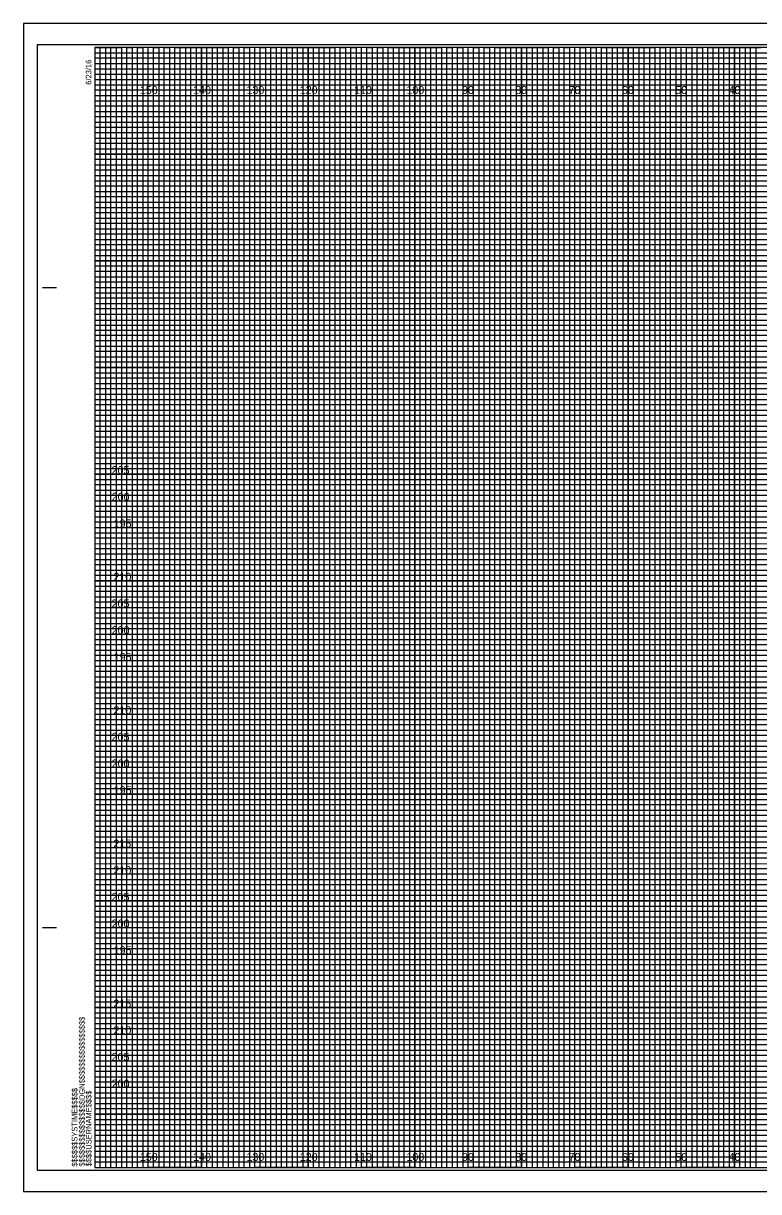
# Model space of a CAD drawing. Extents: x -13 to 323, y -5 to 434.
# Drawn here: x -13.4 to 124.5, y 215.5 to 434.5 of the extents above; entities that cross this region are included whole.
import ezdxf

# ---------------------------------------------------------------- set-up
doc = ezdxf.new("R2010")
doc.units = 0
for name, color, linetype in [('Prop XS Elevation Labels', 7, 'Continuous'), ('Prop XS Offset Labels', 7, 'Continuous'), ('Sheet Cross Section CELL', 7, 'Continuous'), ('Sheet Cross Section Grid Major CELL', 7, 'Continuous'), ('Sheet Cross Section Grid Middle CELL', 7, 'Continuous'), ('Sheet Cross Section Grid Minor 1 CELL', 7, 'Continuous'), ('Sheet Cross Section Grid Minor 2 CELL', 7, 'Continuous'), ('Sheet Cutting Line CELL', 7, 'Continuous'), ('Sheet DOT Grid CELL', 7, 'Continuous'), ('Sheet Plot Border Inside CELL', 7, 'Continuous'), ('Sheet Plot Border Outside CELL', 7, 'Continuous')]:
    doc.layers.add(name, color=color, linetype=linetype)

msp = doc.modelspace()

# ---------------------------------------------------------------- linework, layer by layer
at = {"layer": 'Sheet Cross Section CELL'}
for p, q in [((-9.8, 385), (-7.3, 385)), ((-9.7, 385), (-7.2, 385)), ((-9.8, 265), (-7.3, 265)), ((-9.7, 265), (-7.2, 265)), ((0, 220), (0, 220)), ((0, 220), (0, 220)), ((0, 220), (0, 220)), ((0, 220), (0, 220)), ((0, 220), (0, 220)), ((0, 220), (0, 220)), ((0, 220), (0, 220))]:
    msp.add_line(p, q, dxfattribs=at)
msp.add_lwpolyline([(320, 430), (0, 430), (0, 220), (320, 220)], close=True, dxfattribs=at)
at = {"layer": 'Sheet Cross Section Grid Major CELL'}
for p, q in [((10, 430), (0, 430)), ((10, 220), (10, 430)), ((30, 430), (20, 430)), ((20, 430), (20, 220)), ((30, 220), (30, 430)), ((50, 430), (40, 430)), ((40, 430), (40, 220)), ((50, 220), (50, 430)), ((70, 430), (60, 430)), ((60, 430), (60, 220)), ((70, 220), (70, 430)), ((90, 430), (80, 430)), ((80, 430), (80, 220)), ((90, 220), (90, 430)), ((110, 430), (100, 430)), ((100, 430), (100, 220)), ((110, 220), (110, 430)), ((130, 430), (120, 430)), ((120, 430), (120, 220)), ((20, 220), (10, 220)), ((40, 220), (30, 220)), ((60, 220), (50, 220)), ((80, 220), (70, 220)), ((100, 220), (90, 220)), ((120, 220), (110, 220))]:
    msp.add_line(p, q, dxfattribs=at)
for points in [[(0, 420), (320, 420), (320, 410), (0, 410)], [(0, 400), (320, 400), (320, 390), (0, 390)], [(0, 380), (320, 380), (320, 370), (0, 370)], [(0, 360), (320, 360), (320, 350), (0, 350)], [(0, 340), (320, 340), (320, 330), (0, 330)], [(0, 320), (320, 320), (320, 310), (0, 310)], [(0, 300), (320, 300), (320, 290), (0, 290)], [(0, 280), (320, 280), (320, 270), (0, 270)], [(0, 260), (320, 260), (320, 250), (0, 250)], [(0, 240), (320, 240), (320, 230), (0, 230)]]:
    msp.add_lwpolyline(points, dxfattribs=at)
at = {"layer": 'Sheet Cross Section Grid Middle CELL'}
for points in [[(0, 430), (5, 430), (5, 220), (15, 220), (15, 430), (25, 430), (25, 220), (35, 220), (35, 430), (45, 430), (45, 220), (55, 220), (55, 430), (65, 430), (65, 220), (75, 220), (75, 430), (85, 430), (85, 220), (95, 220), (95, 430), (105, 430), (105, 220), (115, 220), (115, 430), (125, 430)], [(0, 425), (275, 425)], [(0, 405), (320, 405), (320, 415), (0, 415)], [(0, 385), (320, 385), (320, 395), (0, 395)], [(0, 365), (320, 365), (320, 375), (0, 375)], [(0, 345), (320, 345), (320, 355), (0, 355)], [(0, 325), (320, 325), (320, 335), (0, 335)], [(0, 305), (320, 305), (320, 315), (0, 315)], [(0, 285), (320, 285), (320, 295), (0, 295)], [(0, 265), (320, 265), (320, 275), (0, 275)], [(0, 245), (320, 245), (320, 255), (0, 255)], [(0, 225), (320, 225), (320, 235), (0, 235)]]:
    msp.add_lwpolyline(points, dxfattribs=at)
at = {"layer": 'Sheet Cross Section Grid Minor 1 CELL'}
for p, q in [((0, 429), (260, 429)), ((260, 427.98), (0, 427.98)), ((0, 427.98), (0, 427)), ((0, 427), (260, 427)), ((260, 425.89), (0, 425.89)), ((0, 425.89), (0, 424)), ((0, 424), (320, 424))]:
    msp.add_line(p, q, dxfattribs=at)
for points in [[(0, 423), (270, 423), (320, 423), (320, 422), (0, 422)], [(0, 421), (320, 421), (320, 419), (0, 419)], [(0, 418), (320, 418), (320, 417), (0, 416.98)], [(0, 416), (320, 416), (320, 414), (0, 414)], [(0, 413), (320, 413), (320, 412), (0, 412)], [(0, 411), (320, 411), (320, 409), (0, 409)], [(0, 408), (320, 408), (320, 407), (0, 407)], [(0, 406), (320, 406), (320, 404), (0, 404)], [(0, 403), (320, 403), (320, 402), (0, 402)], [(0, 401), (320, 401), (320, 399), (0, 399)], [(0, 398), (320, 398), (320, 397), (0, 397)], [(0, 396), (320, 396), (320, 393.95), (320, 393), (320, 392), (0, 392)], [(0, 394), (320, 394), (320, 393), (0, 393)], [(0, 391), (320, 391), (320, 389), (0, 389.03)], [(0, 389.03), (320, 389), (320, 388), (0, 388)], [(0, 387), (320, 387), (320, 386), (0, 386)], [(0, 384), (320, 384), (320, 383), (0, 383)], [(0, 382), (320, 382), (320, 381), (0, 381)], [(-0.07, 378.89), (320, 378.89), (320, 377.88), (-0.07, 377.88)], [(0, 377), (320, 377), (320, 376), (0, 376)], [(0, 374), (320, 374), (320, 373), (0, 373)], [(0, 372), (320, 372), (320, 371), (0, 371)], [(0, 369), (320, 369), (320, 368), (0, 368)], [(0, 367), (320, 367), (320, 366), (0, 366)], [(0, 364), (320, 364), (320, 363), (0, 363)], [(0, 362), (320, 362), (320, 361), (0, 361)], [(0, 359), (320, 359), (319.99, 357.98), (0, 358)], [(0, 357), (320, 357), (320, 356), (0, 356)], [(0, 354), (320, 354), (320, 353), (0, 353)], [(0, 352), (320, 352), (320, 351), (0, 351)], [(0, 349), (320, 349), (320, 348), (0, 348)], [(0, 347), (320, 347), (320, 346), (0, 346)], [(0, 344), (320, 344), (320, 343), (0, 343)], [(0, 342), (320, 342), (320, 341), (0, 341)], [(0, 339), (320, 339), (320, 338), (0, 338)], [(0, 336.99), (320.07, 336.91), (320, 336), (0, 336)], [(0, 334), (320, 334), (320, 333), (0, 333)], [(0, 332), (320, 332), (320, 331), (0, 331)], [(0, 329), (320, 329), (320, 328), (0, 328)], [(0, 327), (320, 327), (320, 326), (0, 326)], [(0, 324), (320, 324), (320, 323), (0, 323)], [(0, 322), (320, 322), (320, 321), (0, 321)], [(0, 319), (320, 319), (320, 318), (0, 318)], [(0, 317), (320, 317), (320, 316), (0, 316)], [(0, 314), (320, 314), (320, 313), (0, 313)], [(0, 312), (320, 312), (320, 311), (0, 311)], [(0, 309), (320, 309), (320, 308), (0, 308)], [(0, 307), (320, 307), (320, 306), (0, 306)], [(0, 304), (320, 304), (320, 303), (0, 303)], [(0, 302), (320, 302), (320, 301), (0, 301)], [(0, 299), (320, 299), (319.99, 297.98), (0, 298)], [(0, 297), (320, 297), (320, 296), (0, 296)], [(0, 294), (320, 294), (320, 293), (0, 293)], [(0, 292), (320, 292), (320, 291), (0, 291)], [(0, 289), (320, 289), (320, 288), (0, 288)], [(0, 287), (320, 287), (320, 286), (0, 286)], [(0, 284), (320, 284), (320, 283), (0, 283)], [(0, 282), (320, 282), (320, 281), (0, 281)], [(0, 279), (320, 279), (320, 278), (0, 278)], [(0, 276.99), (320.07, 276.91), (320, 276), (0, 276)], [(0, 274), (320, 274), (320, 273), (0, 273)], [(0, 272), (320, 272), (320, 271), (0, 271)], [(0, 269), (320, 269), (320, 268), (0, 268)], [(0, 267), (320, 267), (320, 266), (0, 266)], [(0, 264), (320, 264), (320, 263), (0, 263)], [(0, 262), (320, 262), (320, 261), (0, 261)], [(0, 259), (320, 259), (320, 258), (0, 258)], [(0, 257), (320, 257), (320, 256), (0, 256)], [(0, 254), (320, 254), (320, 253), (0, 253)], [(0, 252), (320, 252), (320, 251), (0, 251)], [(0, 249), (320, 249), (320, 248), (0, 248)], [(0, 247), (320, 247), (320, 246), (0, 246)], [(0, 244), (320, 244), (320, 243), (0, 243)], [(0, 242), (320, 242), (320, 241), (0, 241)], [(0, 239), (320, 239), (320, 238), (0, 238)], [(0, 237), (320, 237), (320, 236), (0, 236)], [(0, 234), (320, 234), (320, 233), (0, 233)], [(0, 232), (320, 232), (320, 231), (0, 231)], [(0, 229), (320, 229), (320, 228), (0, 228)], [(0, 227), (320, 227), (320, 226), (0, 226)], [(0, 224), (320, 224), (320, 223), (0, 223)], [(0, 222), (320, 222), (320, 221), (0, 221)]]:
    msp.add_lwpolyline(points, dxfattribs=at)
at = {"layer": 'Sheet Cross Section Grid Minor 2 CELL'}
for points in [[(0, 220), (1, 220), (1, 430), (2, 430), (2, 220)], [(2, 220), (3, 220), (3, 430), (4, 430), (4, 220)], [(5, 220), (6, 220), (6, 430), (7, 430), (7, 220)], [(7, 220), (8, 220), (8, 430), (9, 430), (9, 220)], [(10, 220), (11, 220), (11, 430), (12, 430), (12, 220)], [(12, 220), (13, 220), (13, 430), (14, 430), (14, 220)], [(15, 220), (16, 220), (16, 430), (17, 430), (17, 220)], [(17, 220), (18, 220), (18, 430), (19, 430), (19, 220)], [(20, 220), (21, 220), (21, 430), (22, 430), (22, 220)], [(22, 220), (23, 220), (23, 430), (24, 430), (24, 220)], [(25, 220), (26, 220), (26, 430), (27, 430), (27, 220)], [(27, 220), (28, 220), (28, 430), (29, 430), (29, 220)], [(30, 220), (31, 220), (31, 430), (32, 430), (32, 220)], [(32, 220), (33, 220), (33, 430), (34, 430), (34, 220)], [(35, 220), (36, 220), (36, 430), (37, 430), (37, 220)], [(37, 220), (38, 220), (38, 430), (39, 430), (39, 220)], [(40, 220), (41, 220), (41, 430), (42, 430), (42, 220)], [(42, 220), (43, 220), (43, 430), (44, 430), (44, 220)], [(45, 220), (46, 220), (46, 430), (47, 430), (47, 220)], [(47, 220), (48, 220), (48, 430), (49, 430), (49, 220)], [(50, 220), (51, 220), (51, 430), (52, 430), (52, 220)], [(52, 220), (53, 220), (53, 430), (54, 430), (54, 220)], [(55, 220), (56, 220), (56, 430), (57, 430), (57, 220)], [(57, 220), (58, 220), (58, 430), (59, 430), (59, 220)], [(60, 220), (61, 220), (61, 430), (62, 430), (62, 220)], [(62, 220), (63, 220), (63, 430), (64, 430), (64, 220)], [(65, 220), (66, 220), (66, 430), (67, 430), (67, 220)], [(67, 220), (68, 220), (68, 430), (69, 430), (69, 220)], [(70, 220), (71, 220), (71, 430), (72, 430), (72, 220)], [(72, 220), (73, 220), (73, 430), (74, 430), (74, 220)], [(75, 220), (76, 220), (76, 430), (77, 430), (77, 220)], [(77, 220), (78, 220), (78, 430), (79, 430), (79, 220)], [(80, 220), (81, 220), (81, 430), (82, 430), (82, 220)], [(82, 220), (83, 220), (83, 430), (84, 430), (84, 220)], [(85, 220), (86, 220), (86, 430), (87, 430), (87, 220)], [(87, 220), (88, 220), (88, 430), (89, 430), (89, 220)], [(90, 220), (91, 220), (91, 430), (92, 430), (92, 220)], [(92, 220), (93, 220), (93, 430), (94, 430), (94, 220)], [(95, 220), (96, 220), (96, 430), (97, 430), (97, 220)], [(97, 220), (98, 220), (98, 430), (99, 430), (99, 220)], [(100, 220), (101, 220), (101, 430), (102, 430), (102, 220)], [(102, 220), (103, 220), (103, 430), (104, 430), (104, 220)], [(105, 220), (106, 220), (106, 430), (107, 430), (107, 220)], [(107, 220), (108, 220), (108, 430), (109, 430), (109, 220)], [(110, 220), (111, 220), (111, 430), (112, 430), (112, 220)], [(112, 220), (113, 220), (113, 430), (114, 430), (114, 220)], [(115, 220), (116, 220), (116, 430), (117, 430), (117, 220)], [(117, 220), (118, 220), (118, 430), (119, 430), (119, 220)], [(120, 220), (121, 220), (121, 430), (122, 430), (122, 220)], [(122, 220), (123, 220), (123, 430), (124, 430), (124, 220)]]:
    msp.add_lwpolyline(points, dxfattribs=at)
at = {"layer": 'Sheet Cutting Line CELL'}
for p, q in [((323.3, 434.5), (-13.4, 434.5)), ((-13.4, 434.5), (-13.4, 215.5)), ((-13.4, 215.5), (323.3, 215.5))]:
    msp.add_line(p, q, dxfattribs=at)
at = {"layer": 'Sheet DOT Grid CELL'}
for p, q in [((10, 220), (10, 430)), ((20, 220), (20, 430)), ((30, 220), (30, 430)), ((40, 220), (40, 430)), ((50, 220), (50, 430)), ((60, 220), (60, 430)), ((70, 220), (70, 430)), ((80, 220), (80, 430)), ((90, 220), (90, 430)), ((100, 220), (100, 430)), ((110, 220), (110, 430)), ((120, 220), (120, 430)), ((0, 420), (320, 420)), ((0, 410), (320, 410)), ((0, 400), (320, 400)), ((0, 390), (320, 390)), ((0, 380), (320, 380)), ((0, 370), (320, 370)), ((0, 360), (320, 360)), ((0, 350), (320, 350)), ((0, 340), (320, 340)), ((0, 330), (320, 330)), ((0, 320), (320, 320)), ((0, 310), (320, 310)), ((0, 300), (320, 300)), ((0, 290), (320, 290)), ((0, 280), (320, 280)), ((0, 270), (320, 270)), ((0, 260), (320, 260)), ((0, 250), (320, 250)), ((0, 240), (320, 240)), ((0, 230), (320, 230))]:
    msp.add_line(p, q, dxfattribs=at)
at = {"layer": 'Sheet Plot Border Inside CELL'}
msp.add_lwpolyline([(-10.8, 219.5), (322.4, 219.5), (322.4, 430.5), (-10.8, 430.5)], close=True, dxfattribs=at)
at = {"layer": 'Sheet Plot Border Outside CELL'}
msp.add_lwpolyline([(-13.4, 215.5), (323.3, 215.5), (323.3, 434.5), (-13.4, 434.5)], close=True, dxfattribs=at)

# ---------------------------------------------------------------- texts
at = {"layer": 'Prop XS Elevation Labels'}
for s, p in [('205', (3.15, 350)), ('200', (3.17, 345)), ('195', (3.55, 340)), ('210', (3.5, 330)), ('205', (3.15, 325)), ('200', (3.17, 320)), ('195', (3.55, 315)), ('210', (3.5, 305)), ('205', (3.15, 300)), ('200', (3.17, 295)), ('195', (3.55, 290)), ('215', (3.48, 280)), ('210', (3.5, 275)), ('205', (3.15, 270)), ('200', (3.17, 265)), ('195', (3.55, 260)), ('215', (3.48, 250)), ('210', (3.5, 245)), ('205', (3.15, 240)), ('200', (3.17, 235))]:
    msp.add_text(s, height=1.5, dxfattribs=at).set_placement(p)
at = {"layer": 'Prop XS Offset Labels'}
for s, p in [('150', (8.44, 421.25)), ('140', (18.44, 421.25)), ('130', (28.44, 421.25)), ('120', (38.44, 421.25)), ('110', (48.62, 421.25)), ('100', (58.44, 421.25)), ('90', (68.86, 421.25)), ('80', (78.86, 421.25)), ('70', (88.86, 421.25)), ('60', (98.86, 421.25)), ('50', (108.86, 421.25)), ('40', (118.86, 421.25)), ('150', (8.44, 221.25)), ('140', (18.44, 221.25)), ('130', (28.44, 221.25)), ('120', (38.44, 221.25)), ('110', (48.62, 221.25)), ('100', (58.44, 221.25)), ('90', (68.86, 221.25)), ('80', (78.86, 221.25)), ('70', (88.86, 221.25)), ('60', (98.86, 221.25)), ('50', (108.86, 221.25)), ('40', (118.86, 221.25))]:
    msp.add_text(s, height=1.5, dxfattribs=at).set_placement(p)
at = {"layer": 'Sheet Cross Section CELL'}
for s, p in [('6/23/16', (-0.65, 423)), ('$$$$$$$$$$$$$$$$DGN$$$$$$$$$$$$$$$$', (-1.88, 220.18)), ('$$$$$$SYSTIME$$$$$', (-3.26, 220.18)), ('$$$$USERNAME$$$$', (-0.62, 220.23))]:
    msp.add_text(s, height=1.05, rotation=90, dxfattribs=at).set_placement(p)

doc.saveas('drawing.dxf')
